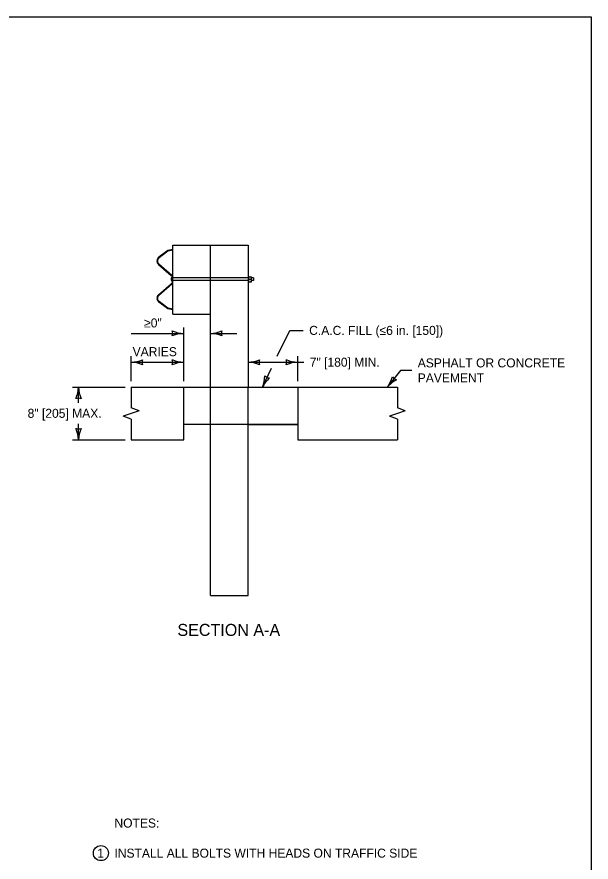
# Model space of a CAD drawing. Extents: x 49991.4 to 50021, y 49987.6 to 50011.4.
# Drawn here: x 50012.93 to 50016.75, y 49993.38 to 49999 of the extents above; entities that cross this region are included whole.
import ezdxf

# ---------------------------------------------------------------- set-up
doc = ezdxf.new("R2010")
doc.units = 0
for name, color, linetype in [('Level 1', 7, 'Continuous'), ('Level 2', 7, 'Continuous'), ('Level 3', 7, 'Continuous'), ('Level 4', 7, 'Continuous'), ('Level 6', 7, 'Continuous')]:
    doc.layers.add(name, color=color, linetype=linetype)

msp = doc.modelspace()

# ---------------------------------------------------------------- linework, layer by layer
at = {"layer": 'Level 1'}
for p, q in [((50013.9338, 49997.4459), (50013.8741, 49997.4012)), ((50013.9354, 49997.4423), (50013.8765, 49997.3981)), ((50013.9678, 49997.452), (50013.9338, 49997.4459)), ((50013.9678, 49997.4479), (50013.9354, 49997.4423)), ((50013.9678, 49997.4816), (50014.2961, 49997.4816)), ((50013.9678, 49997.0226), (50013.9678, 49997.4816)), ((50014.2179, 49996.5367), (50014.2179, 49997.4816)), ((50014.2961, 49997.4816), (50014.3897, 49997.4816)), ((50014.3897, 49997.4816), (50014.468, 49997.4816)), ((50014.468, 49997.4816), (50014.468, 49996.5367)), ((50013.8724, 49997.3534), (50013.9575, 49997.2793)), ((50013.875, 49997.3564), (50013.9601, 49997.2822)), ((50014.468, 49997.2755), (50014.4699, 49997.2755)), ((50014.4699, 49997.2755), (50014.4699, 49997.2344)), ((50013.8724, 49997.151), (50013.9573, 49997.225)), ((50013.875, 49997.1481), (50013.9614, 49997.2235)), ((50013.9659, 49997.2551), (50013.9562, 49997.2551)), ((50014.468, 49997.2344), (50014.4699, 49997.2344)), ((50014.4699, 49997.2716), (50014.4915, 49997.2716)), ((50014.4699, 49997.2551), (50014.4915, 49997.2551)), ((50014.4699, 49997.2386), (50014.4915, 49997.2386)), ((50014.4915, 49997.2386), (50014.4915, 49997.2716)), ((50014.5046, 49997.2647), (50014.4915, 49997.2647)), ((50014.5046, 49997.2453), (50014.4915, 49997.2453)), ((50014.5046, 49997.2647), (50014.5046, 49997.2453)), ((50013.9354, 49997.0617), (50013.8765, 49997.1063)), ((50013.9338, 49997.058), (50013.8741, 49997.1032)), ((50013.9678, 49997.052), (50013.9338, 49997.058)), ((50013.9678, 49997.056), (50013.9354, 49997.0617)), ((50013.9678, 49997.0226), (50014.2179, 49997.0226)), ((50013.6903, 49996.5367), (50014.2179, 49996.5367)), ((50014.0403, 49996.1867), (50014.0403, 49996.5367)), ((50014.468, 49996.5367), (50015.4617, 49996.5367)), ((50014.7985, 49996.5367), (50014.7985, 49996.1867)), ((50014.2179, 49996.2879), (50014.0403, 49996.2879)), ((50014.468, 49996.2879), (50014.7985, 49996.2879)), ((50013.6903, 49996.1867), (50014.0403, 49996.1867)), ((50014.7985, 49996.1867), (50015.4617, 49996.1867))]:
    msp.add_line(p, q, dxfattribs=at)
for points in [[(49999.3835, 49998.9992), (50016.7501, 49998.9992), (50016.7501, 49987.7988), (49999.3835, 49987.7988)], [(50014.0403, 49996.5367), (50014.7985, 49996.5367), (50014.7985, 49996.2879), (50014.0403, 49996.2879)]]:
    msp.add_lwpolyline(points, close=True, dxfattribs=at)
for centre, radius, start, end in [((50013.8926, 49997.3766), 0.0308, 126.8969, 228.9393), ((50013.8926, 49997.3766), 0.0269, 126.8969, 228.9393), ((50013.9374, 49997.2562), 0.0306, 5.9023, 48.9393), ((50013.9374, 49997.2562), 0.0345, 28.1043, 48.9393), ((50013.9374, 49997.2482), 0.0306, 310.4718, 354.0977), ((50013.9374, 49997.2482), 0.0345, 314.1015, 331.8957), ((50013.8926, 49997.1278), 0.0308, 131.0607, 233.1031), ((50013.8926, 49997.1278), 0.0269, 131.0607, 233.1031)]:
    msp.add_arc(centre, radius, start, end, dxfattribs=at)
for centre, major_axis, ratio, start_param, end_param in [((50013.9659, 49997.2549), (0, 0.0146), 0.663267, 0.091019, 3.253139), ((50014.4831, 49997.2633), (0.00829, 0.00104), 0.990733, 4.594607, 7.611796), ((50014.4831, 49997.2468), (-0.00829, -0.00104), 0.990733, 1.560784, 4.582629)]:
    msp.add_ellipse(centre, major_axis=major_axis, ratio=ratio, start_param=start_param, end_param=end_param, dxfattribs=at)
at = {"layer": 'Level 2'}
msp.add_circle((50013.4892, 49993.4385), 0.05, dxfattribs=at)
at = {"layer": 'Level 3'}
for p, q in [((50013.6903, 49996.8943), (50014.0403, 49996.8943)), ((50014.0403, 49996.5767), (50014.0403, 49996.9343)), ((50014.2179, 49996.8943), (50014.3929, 49996.8943)), ((50014.6626, 49996.7431), (50014.7451, 49996.9146)), ((50014.7451, 49996.9146), (50014.8346, 49996.9146)), ((50013.6903, 49996.5767), (50013.6903, 49996.7431)), ((50014.7985, 49996.5767), (50014.7985, 49996.7431)), ((50013.6903, 49996.7031), (50014.0403, 49996.7031)), ((50014.468, 49996.7031), (50014.6433, 49996.7031)), ((50014.5632, 49996.5367), (50014.6241, 49996.6631)), ((50014.6433, 49996.7031), (50014.8385, 49996.7031)), ((50015.4829, 49996.6485), (50015.3939, 49996.5367)), ((50015.5568, 49996.6485), (50015.4829, 49996.6485)), ((50013.3003, 49996.5367), (50013.6503, 49996.5367)), ((50013.3403, 49996.4332), (50013.3403, 49996.5367)), ((50013.3403, 49996.1867), (50013.3403, 49996.2932)), ((50013.3003, 49996.1867), (50013.6503, 49996.1867))]:
    msp.add_line(p, q, dxfattribs=at)
for centre, radius, start, end in [((50014.0494, 49997.1164), 0.2223, 247.456, 267.6395), ((50013.912, 49996.8943), 0.0548, 342.1388, 17.8612), ((50014.0517, 49996.6616), 0.233, 92.8273, 112.0772), ((50014.2064, 49997.127), 0.233, 272.8273, 292.0772), ((50014.2088, 49996.6722), 0.2223, 67.456, 87.6395), ((50014.3462, 49996.8943), 0.0548, 162.1388, 197.8612), ((50013.6788, 49996.9358), 0.233, 272.8273, 292.0772), ((50013.8185, 49996.7031), 0.0548, 162.1388, 197.8612), ((50014.0494, 49996.9253), 0.2223, 247.456, 267.6395), ((50013.912, 49996.7031), 0.0548, 342.1388, 17.8612), ((50014.4565, 49996.9358), 0.233, 272.8273, 292.0772), ((50014.5963, 49996.7031), 0.0548, 162.1388, 197.8612), ((50014.8076, 49996.9253), 0.2223, 247.456, 267.6395), ((50014.6702, 49996.7031), 0.0548, 342.1388, 17.8612), ((50013.6811, 49996.481), 0.2223, 67.456, 87.6395), ((50014.0517, 49996.4704), 0.233, 92.8273, 112.0772), ((50014.4589, 49996.481), 0.2223, 67.456, 87.6395), ((50014.8099, 49996.4704), 0.233, 92.8273, 112.0772), ((50014.3475, 49996.6246), 0.233, 337.8273, 357.0772), ((50014.7607, 49996.4345), 0.2223, 132.456, 152.6395), ((50014.6174, 49996.6529), 0.0548, 227.1388, 262.8612), ((50015.2047, 49996.6726), 0.233, 324.303, 343.5529), ((50015.4738, 49996.637), 0.0548, 213.6145, 249.3369), ((50015.562, 49996.3912), 0.2223, 118.9317, 139.1152), ((50013.1075, 49996.5482), 0.233, 337.9228, 357.1727), ((50013.5624, 49996.5458), 0.2223, 182.3605, 202.544), ((50013.3403, 49996.4085), 0.0548, 72.1388, 107.8612), ((50013.3403, 49996.3149), 0.0548, 252.1388, 287.8612), ((50013.1075, 49996.1752), 0.233, 2.8273, 22.0772), ((50013.5624, 49996.1775), 0.2223, 157.456, 177.6395)]:
    msp.add_arc(centre, radius, start, end, dxfattribs=at)
at = {"layer": 'Level 4'}
for p, q in [((50014.468, 49997.2647), (50013.9678, 49997.2647)), ((50014.468, 49997.2453), (50013.9678, 49997.2453)), ((50014.2179, 49995.1519), (50014.2179, 49996.5367)), ((50014.468, 49995.1519), (50014.468, 49996.5367)), ((50014.468, 49995.1519), (50014.468, 49996.5367)), ((50014.2179, 49995.1519), (50014.468, 49995.1519)), ((50014.2179, 49995.1519), (50014.468, 49995.1519))]:
    msp.add_line(p, q, dxfattribs=at)
at = {"layer": 'Level 6'}
for p, q in [((50013.6903, 49996.5367), (50013.6903, 49996.3988)), ((50015.4617, 49996.5367), (50015.4617, 49996.3988)), ((50013.7427, 49996.3803), (50013.6903, 49996.3988)), ((50013.7427, 49996.3803), (50013.6903, 49996.3617)), ((50015.5141, 49996.3803), (50015.4617, 49996.3988)), ((50015.5141, 49996.3803), (50015.4617, 49996.3617)), ((50013.6903, 49996.3617), (50013.638, 49996.3432)), ((50013.6903, 49996.3246), (50013.638, 49996.3432)), ((50013.6903, 49996.3246), (50013.6903, 49996.1867)), ((50015.4617, 49996.3617), (50015.4094, 49996.3432)), ((50015.4617, 49996.3246), (50015.4094, 49996.3432)), ((50015.4617, 49996.3246), (50015.4617, 49996.1867))]:
    msp.add_line(p, q, dxfattribs=at)

# ---------------------------------------------------------------- texts
at = {"layer": 'Level 2'}
for s, height, p in [('≥0"', 0.06, (50013.7766, 49996.9343)), ('C.A.C. FILL (≤6 in. [150])', 0.06, (50014.8746, 49996.8846)), ('VARIES', 0.06, (50013.7002, 49996.7431)), ('7" [180] MIN.', 0.06, (50014.8785, 49996.6731)), ('ASPHALT OR CONCRETE', 0.06, (50015.5968, 49996.6685)), ('PAVEMENT', 0.06, (50015.5968, 49996.5685)), ('8" [205] MAX.', 0.06, (50013.0016, 49996.3332)), ('SECTION A-A', 0.08, (50013.9981, 49994.8829)), ('NOTES:', 0.06, (50013.5792, 49993.6085)), ('1', 0.06, (50013.4652, 49993.4085)), ('INSTALL ALL BOLTS WITH HEADS ON TRAFFIC SIDE ', 0.06, (50013.5792, 49993.4085))]:
    msp.add_text(s, height=height, dxfattribs=at).set_placement(p)

doc.saveas('drawing.dxf')
